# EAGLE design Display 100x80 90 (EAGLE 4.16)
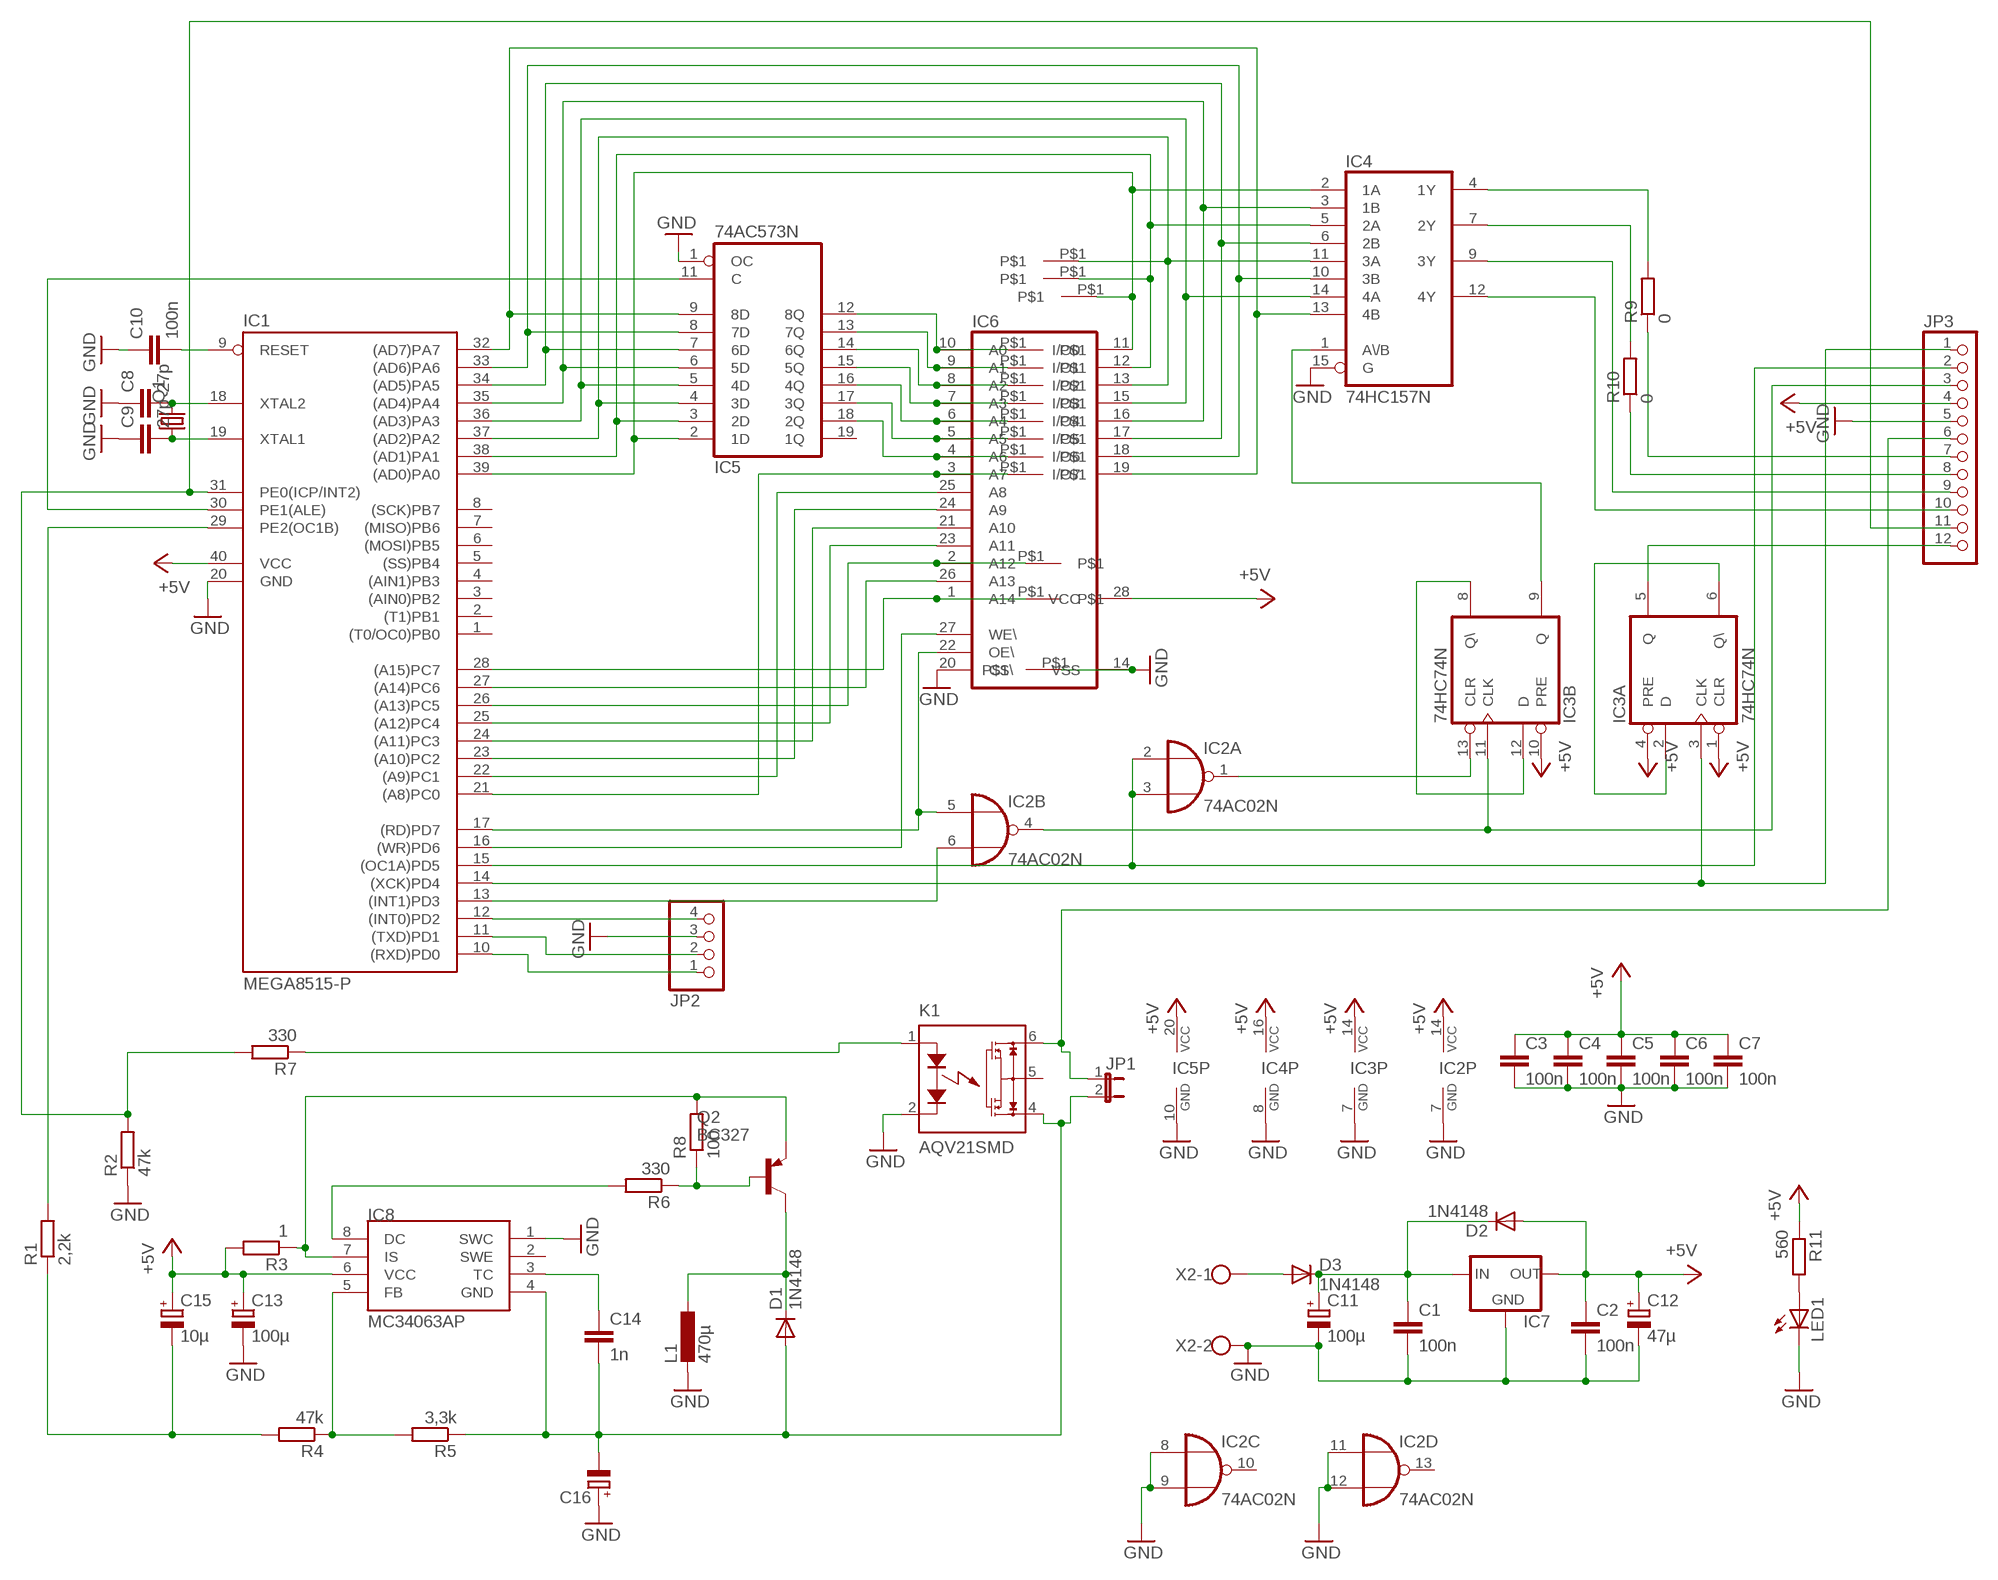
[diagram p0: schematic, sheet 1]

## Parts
C1  100n  C-EUC1206  [C1206]
C2  100n  C-EUC1206  [C1206]
C3  100n  C-EUC1206  [C1206]
C4  100n  C-EUC1206  [C1206]
C5  100n  C-EUC1206  [C1206]
C6  100n  C-EUC1206  [C1206]
C7  100n  C-EUC1206  [C1206]
C8  27p  C-EUC1206  [C1206]
C9  27p  C-EUC1206  [C1206]
C10  100n  C-EUC1206  [C1206]
C11  100µ  CPOL-EUE5-5  [E5-5]
C12  47µ  CPOL-EUE5-5  [E5-5]
C13  100µ  CPOL-EUE5-5  [E5-5]
C14  1n  C-EUC1206  [C1206]
C15  10µ  CPOL-EUE5-5  [E5-5]
C16  CPOL-EUE5-5  [E5-5]
D1  1N4148  [DO35-10]
D2  1N4148  [DO35-10]
D3  1N4148  [DO35-10]
IC1  MEGA8515-P  [DIL40]
IC2  74AC02N  [DIL14]
IC3  74HC74N  [DIL14]
IC4  74HC157N  [DIL16]
IC5  74AC573N  [DIL20]
IC6  62256P  [DIL28-6]
IC7  78XXS  [78XXS]
IC8  MC34063AP  [DIL08]
JP1  JP1E  [JP1]
JP2  PINHD-1X4  [1X04]
JP3  PINHD-1X12  [1X12]
K1  AQV21SMD  [DIL06SMD]
L1  470µ  L-EU0204/7  [0204/7]
LED1  LEDCHIPLED_1206  [CHIPLED_1206]
Q1  CRYSTALHC49U-V  [HC49U-V]
Q2  BC327  [TO92]
R1  2,2k  R-EU_M1206  [M1206]
R2  47k  R-EU_M1206  [M1206]
R3  1  R-EU_M1206  [M1206]
R4  47k  R-EU_M1206  [M1206]
R5  3,3k  R-EU_M1206  [M1206]
R6  330  R-EU_M1206  [M1206]
R7  330  R-EU_M1206  [M1206]
R8  100  R-EU_M1206  [M1206]
R9  0  R-EU_0207/10  [0207/10]
R10  0  R-EU_0207/10  [0207/10]
R11  560  R-EU_M1206  [M1206]
U$2  PAD  [PAD]
U$3  PAD  [PAD]
U$4  PAD  [PAD]
U$5  PAD  [PAD]
U$6  PAD  [PAD]
U$7  PAD  [PAD]
U$8  PAD  [PAD]
U$9  PAD  [PAD]
U$10  PAD  [PAD]
U$11  PAD  [PAD]
U$12  PAD  [PAD]
U$13  PAD  [PAD]
U$14  PAD  [PAD]
U$15  PAD  [PAD]
X2  W237-102  [W237-102]

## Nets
+5V: C2.1 C3.1 C4.1 C5.1 C6.1 C7.1 C12.+ C13.+ C15.+ D2.A IC1.40(VCC) IC2.14(P:VCC) IC3.1(A:CLR) IC3.4(A:PRE) IC3.10(B:PRE) IC3.14(P:VCC) IC4.16(VCC) IC5.20(VCC) IC6.28(VCC) IC7.OUT IC8.6(VCC) JP3.4 R3.2 R11.1
GND: C1.2 C2.2 C3.2 C4.2 C5.2 C6.2 C7.2 C8.1 C9.1 C10.1 C11.- C12.- C13.- C16.+ IC1.20(GND) IC2.7(P:GND) IC2.8(C:I0) IC2.9(C:I1) IC2.11(D:I0) IC2.12(D:I1) IC3.7(P:GND) IC4.8(GND) IC4.15(G) IC5.1(OC) IC5.10(GND) IC6.14(VSS) IC6.20(CS\) IC7.GND IC8.1(SWC) JP2.3 JP3.5 K1.2(K) L1.2 LED1.C R2.1 U$11.P$1 X2.2
N$1: IC1.39((AD0)PA0) IC4.2(1A) IC5.2(1D) IC6.11(I/O0) U$15.P$1
N$2: IC1.38((AD1)PA1) IC4.5(2A) IC5.3(2D) IC6.12(I/O1) U$13.P$1
N$3: IC1.37((AD2)PA2) IC4.11(3A) IC5.4(3D) IC6.13(I/O2) U$8.P$1
N$4: IC1.36((AD3)PA3) IC4.14(4A) IC5.5(4D) IC6.15(I/O3)
N$5: IC1.35((AD4)PA4) IC4.3(1B) IC5.6(5D) IC6.16(I/O4)
N$6: IC1.34((AD5)PA5) IC4.6(2B) IC5.7(6D) IC6.17(I/O5)
N$7: IC1.33((AD6)PA6) IC4.10(3B) IC5.8(7D) IC6.18(I/O6)
N$8: IC1.32((AD7)PA7) IC4.13(4B) IC5.9(8D) IC6.19(I/O7)
N$9: IC5.12(8Q) IC6.10(A0) U$4.P$1
N$10: IC5.13(7Q) IC6.9(A1) U$5.P$1
N$11: IC5.14(6Q) IC6.8(A2) U$6.P$1
N$12: IC5.15(5Q) IC6.7(A3) U$12.P$1
N$13: IC5.16(4Q) IC6.6(A4) U$14.P$1
N$14: IC5.17(3Q) IC6.5(A5) U$7.P$1
N$15: IC5.18(2Q) IC6.4(A6) U$9.P$1
N$16: IC1.21((A8)PC0) IC6.3(A7) U$10.P$1
N$17: IC1.22((A9)PC1) IC6.25(A8)
N$18: IC1.23((A10)PC2) IC6.24(A9)
N$19: IC1.24((A11)PC3) IC6.21(A10)
N$20: IC1.25((A12)PC4) IC6.23(A11)
N$21: IC1.26((A13)PC5) IC6.2(A12) U$3.P$1
N$22: IC1.27((A14)PC6) IC6.26(A13)
N$23: IC1.28((A15)PC7) IC6.1(A14) U$2.P$1
N$24: IC1.16((WR)PD6) IC6.27(WE\)
N$25: IC1.17((RD)PD7) IC2.5(B:I0) IC6.22(OE\)
N$26: IC3.8(B:Q\) IC3.12(B:D)
N$27: IC3.9(B:Q) IC4.1(A\/B)
N$28: IC3.2(A:D) IC3.6(A:Q\)
N$29: IC2.1(A:O) IC3.13(B:CLR)
N$31: IC1.13((INT1)PD3) IC2.6(B:I1)
N$32: C8.2 IC1.18(XTAL2) Q1.2
N$33: C9.2 IC1.19(XTAL1) Q1.1
N$34: C10.2 IC1.9(RESET)
N$35: IC1.31(PE0(ICP/INT2)) JP3.11 R2.2 R7.2
N$36: IC1.15((OC1A)PD5) IC2.2(A:I0) IC2.3(A:I1) JP3.2
N$37: IC1.30(PE1(ALE)) IC5.11(C)
N$38: IC3.5(A:Q) JP3.12
N$39: IC2.4(B:O) IC3.11(B:CLK) JP3.3
N$40: JP3.7 R9.1
N$41: JP3.8 R10.1
N$42: IC4.9(3Y) JP3.9
N$43: IC4.12(4Y) JP3.10
N$45: C14.1 IC8.3(TC)
N$46: C14.2 C16.- D1.A IC8.4(GND) JP1.2 K1.4(D2) R5.1
N$47: C1.1 C11.+ D2.C D3.C IC7.IN
N$48: IC8.5(FB) R4.1 R5.2
N$49: K1.1(A) R7.1
N$50: LED1.A R11.2
N$51: C15.- R1.1 R4.2
N$52: IC1.29(PE2(OC1B)) R1.2
N$53: IC8.8(DC) R6.2
N$54: Q2.2(B) R6.1 R8.1
N$55: IC8.7(IS) Q2.1(E) R3.1 R8.2
N$56: D1.C L1.1 Q2.3(C)
N$57: JP1.1 JP3.6 K1.6(D1)
N$58: IC4.4(1Y) R9.2
N$59: IC4.7(2Y) R10.2
N$60: D3.A X2.1
N$61: IC1.14((XCK)PD4) IC3.3(A:CLK) JP3.1
N$63: IC1.12((INT0)PD2) JP2.4
RXD: IC1.10((RXD)PD0) JP2.1
TXD: IC1.11((TXD)PD1) JP2.2
Unconnected: IC1.1((T0/OC0)PB0) IC1.2((T1)PB1) IC1.3((AIN0)PB2) IC1.4((AIN1)PB3) IC1.5((SS)PB4) IC1.6((MOSI)PB5) IC1.7((MISO)PB6) IC1.8((SCK)PB7) IC2.10(C:O) IC2.13(D:O) IC5.19(1Q) IC8.2(SWE) K1.5(S)

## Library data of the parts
C1-C10 C14 = rcl:C-EU: CAPACITOR, European symbol
C11-C13 C15 C16 = rcl:CPOL-EU: POLARIZED CAPACITOR, European symbol
D1-D3 = diode:1N4148: DIODE
IC1 = atmel:MEGA8515-P: MICROCONTROLLER 8 Kbytes FLASH 512 bytes SRAM 512 bytes EEPROM USART 8-channel 10 bit ADC Source: avr.lbr
IC2 = 74xx-eu:74*02: Quad 2-input NOR gate
IC3 = 74xx-eu:74*74: Dual D type positive edge triggered FLIP FLOP, preset and clear
IC4 = 74xx-eu:74*157: Quadruple 2-line to 1-line data SELECTOR/MULTIPLEXER
IC5 = 74xx-eu:74*573: 8-bit D latch BUS DRIVER
IC6 = memory-hitachi:62256P: MEMORY
IC7 = v-reg:78XXS: VOLTAGE REGULATOR
IC8 = mc34063:MC34063
JP1 = jumper:JP1E: JUMPER
JP2 = pinhead:PINHD-1X4: PIN HEADER
JP3 = pinhead:PINHD-1X12: PIN HEADER
K1 = relay:AQV*: PhotoMOS Relay NAiS Source: http://www.mew-europe.com/.. pti_en.pdf
L1 = rcl:L-EU: INDUCTOR, European symbol
LED1 = led:LED: LED
Q1 = crystal:CRYSTAL: CRYSTAL
Q2 = transistor-pnp:BC327: PNP Transistor
R1-R11 = rcl:R-EU_: RESISTOR, European symbol
U$2-U$15 = special-pad:PAD
X2 = con-wago-500:W237-102: WAGO SCREW CLAMP

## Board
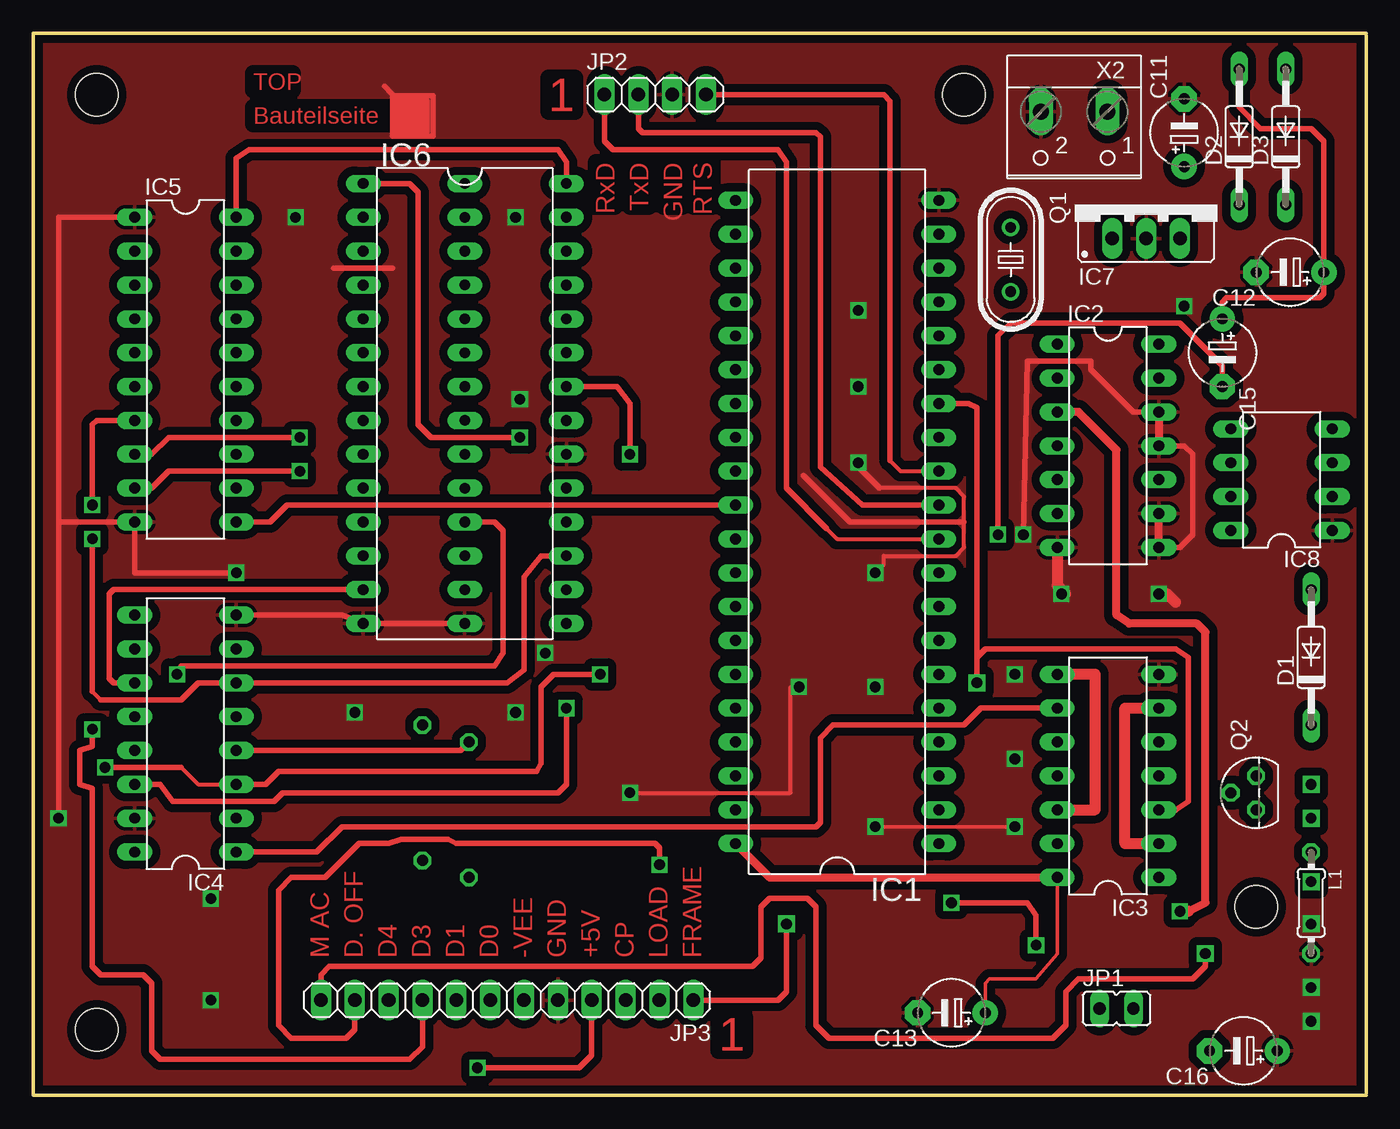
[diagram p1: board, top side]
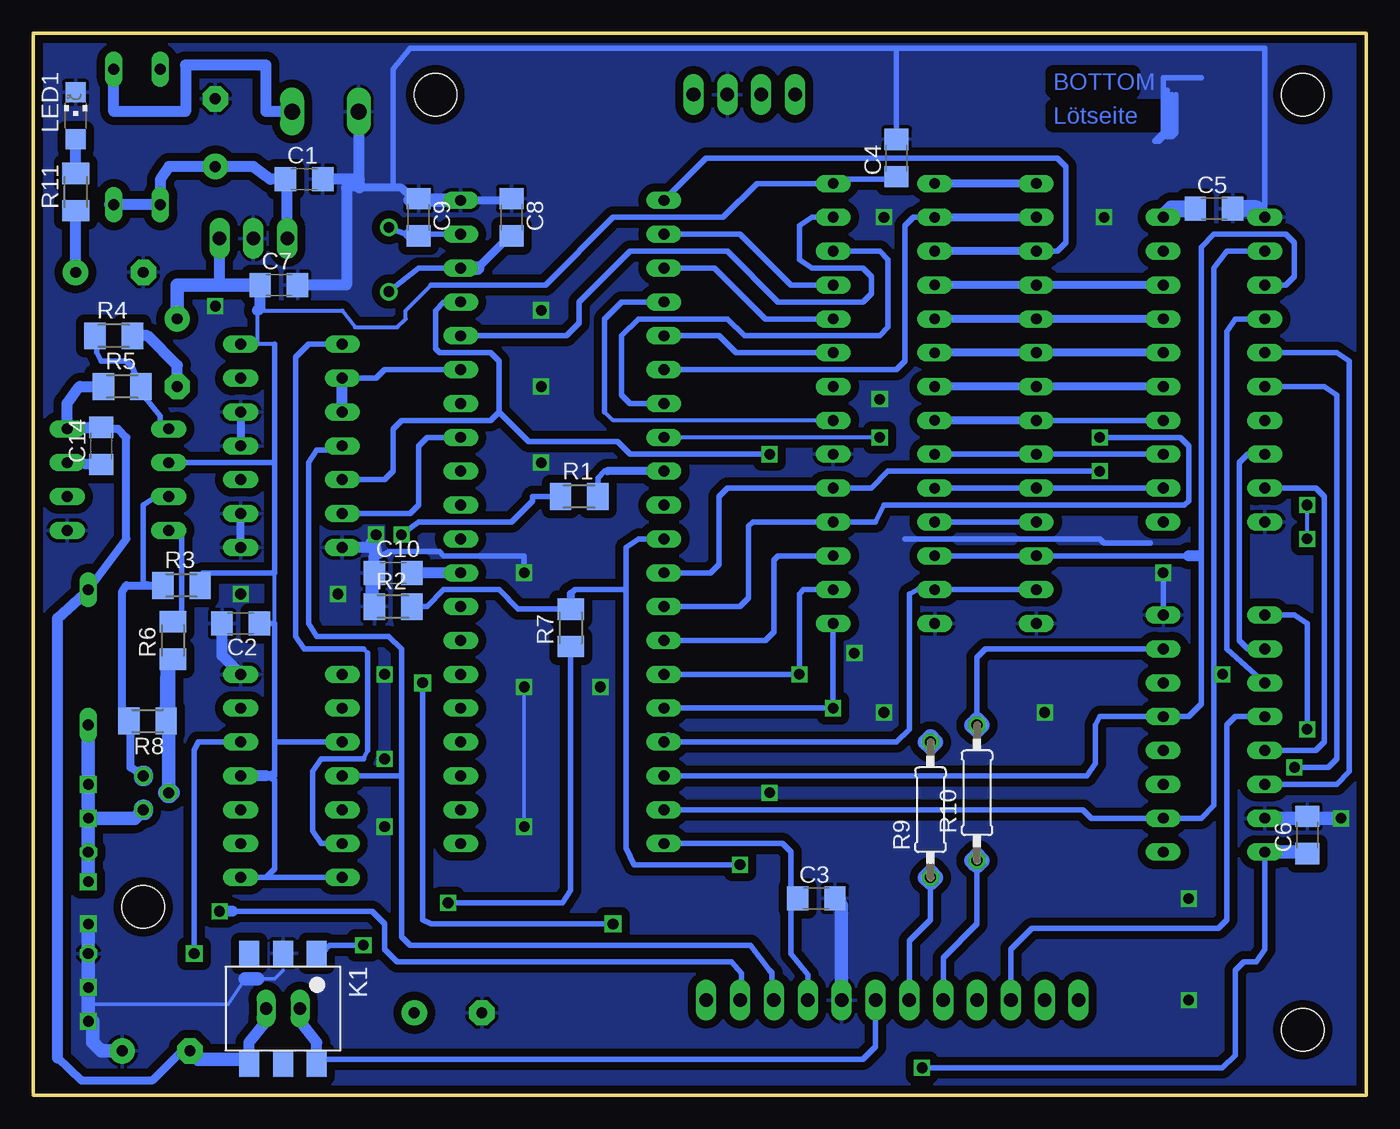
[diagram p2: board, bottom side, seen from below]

Size 100 x 79.68 mm. Coordinates in mm from the lower left corner, seen from the top.
Outline: 99.99,0 0,0 0,79.68 99.99,79.68
Outline: 100,79.53 100,0.15
Copper layers (1*16): Top 0.035mm / dielectric 1.5mm / Bottom 0.035mm
Design rules "default": minimum track width 10mil, minimum drill 24mil, track to track 10mil, track to pad 10mil, pad to pad 10mil, via to via 10mil, smd to smd 10mil, copper to edge 20mil, drill to drill 8mil, minimum pad ring 10mil, minimum via ring 8mil, stop-mask expansion 4mil, vias tented up to drill 0mil, thermal gap 10mil
Holes 3.2 mm at 4.75,75.08 69.83,75.08 4.75,4.92 91.74,14.12

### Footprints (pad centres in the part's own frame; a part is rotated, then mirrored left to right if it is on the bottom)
C1206 = smd 1.6 x 1.8: 1 -1.4,0; 2 1.4,0
E5-5 = drill 0.813 pad 1.905 round: + -2.54,0 | drill 0.813 pad 1.905 octagon: - 2.54,0
DO35-10 = drill 0.813 long: A 5.08,0; C -5.08,0
DIL40 = drill 0.813 long: 1 -24.13,-7.62; 2 -21.59,-7.62; 3 -19.05,-7.62; 4 -16.51,-7.62; 5 -13.97,-7.62; 6 -11.43,-7.62; 7 -8.89,-7.62; 8 -6.35,-7.62; 9 -3.81,-7.62; 10 -1.27,-7.62; 11 1.27,-7.62; 12 3.81,-7.62; 13 6.35,-7.62; 14 8.89,-7.62; 15 11.43,-7.62; 16 13.97,-7.62; 17 16.51,-7.62; 18 19.05,-7.62; 19 21.59,-7.62; 20 24.13,-7.62; 21 24.13,7.62; 22 21.59,7.62; 23 19.05,7.62; 24 16.51,7.62; 25 13.97,7.62; 26 11.43,7.62; 27 8.89,7.62; 28 6.35,7.62; 29 3.81,7.62; 30 1.27,7.62; 31 -1.27,7.62; 32 -3.81,7.62; 33 -6.35,7.62; 34 -8.89,7.62; 35 -11.43,7.62; 36 -13.97,7.62; 37 -16.51,7.62; 38 -19.05,7.62; 39 -21.59,7.62; 40 -24.13,7.62
DIL14 = drill 0.813 long: 1 -7.62,-3.81; 2 -5.08,-3.81; 3 -2.54,-3.81; 4 0,-3.81; 5 2.54,-3.81; 6 5.08,-3.81; 7 7.62,-3.81; 8 7.62,3.81; 9 5.08,3.81; 10 2.54,3.81; 11 0,3.81; 12 -2.54,3.81; 13 -5.08,3.81; 14 -7.62,3.81
DIL16 = drill 0.813 long: 1 -8.89,-3.81; 2 -6.35,-3.81; 3 -3.81,-3.81; 4 -1.27,-3.81; 5 1.27,-3.81; 6 3.81,-3.81; 7 6.35,-3.81; 8 8.89,-3.81; 9 8.89,3.81; 10 6.35,3.81; 11 3.81,3.81; 12 1.27,3.81; 13 -1.27,3.81; 14 -3.81,3.81; 15 -6.35,3.81; 16 -8.89,3.81
DIL20 = drill 0.813 long: 1 -11.43,-3.81; 2 -8.89,-3.81; 3 -6.35,-3.81; 4 -3.81,-3.81; 5 -1.27,-3.81; 6 1.27,-3.81; 7 3.81,-3.81; 8 6.35,-3.81; 9 8.89,-3.81; 10 11.43,-3.81; 11 11.43,3.81; 12 8.89,3.81; 13 6.35,3.81; 14 3.81,3.81; 15 1.27,3.81; 16 -1.27,3.81; 17 -3.81,3.81; 18 -6.35,3.81; 19 -8.89,3.81; 20 -11.43,3.81
DIL28-6 = drill 0.813 long: 1 -16.51,-7.62; 2 -13.97,-7.62; 3 -11.43,-7.62; 4 -8.89,-7.62; 5 -6.35,-7.62; 6 -3.81,-7.62; 7 -1.27,-7.62; 8 1.27,-7.62; 9 3.81,-7.62; 10 6.35,-7.62; 11 8.89,-7.62; 12 11.43,-7.62; 13 13.97,-7.62; 14 16.51,-7.62; 15 16.51,7.62; 16 13.97,7.62; 17 11.43,7.62; 18 8.89,7.62; 19 6.35,7.62; 20 3.81,7.62; 21 1.27,7.62; 22 -1.27,7.62; 23 -3.81,7.62; 24 -6.35,7.62; 25 -8.89,7.62; 26 -11.43,7.62; 27 -13.97,7.62; 28 -16.51,7.62
78XXS = drill 1.016 long: GND 0,-2.54; IN -2.54,-2.54; OUT 2.54,-2.54
DIL08 = drill 0.813 long: 1 -3.81,-3.81; 2 -1.27,-3.81; 3 1.27,-3.81; 4 3.81,-3.81; 5 3.81,3.81; 6 1.27,3.81; 7 -1.27,3.81; 8 -3.81,3.81
JP1 = drill 0.914 long: 1 0,-1.27; 2 0,1.27
1X04 = drill 1.016 long: 1 -3.81,0; 2 -1.27,0; 3 1.27,0; 4 3.81,0
1X12 = drill 1.016 long: 1 -13.97,0; 2 -11.43,0; 3 -8.89,0; 4 -6.35,0; 5 -3.81,0; 6 -1.27,0; 7 1.27,0; 8 3.81,0; 9 6.35,0; 10 8.89,0; 11 11.43,0; 12 13.97,0
DIL06SMD = smd 1.5 x 1.9: 1 -2.54,-4.15; 2 0,-4.15; 3 2.54,-4.15; 4 2.54,4.15; 5 0,4.15; 6 -2.54,4.15
0204/7 = drill 0.813 octagon: 1 -3.81,0; 2 3.81,0
CHIPLED_1206 = smd 1.5 x 1.5: A 0,-1.75; C 0,1.75
HC49U-V = drill 0.813 round: 1 -2.413,0; 2 2.413,0
TO92 = drill 0.813 octagon: 1 1.27,0; 2 0,1.905; 3 -1.27,0
M1206 = smd 1.6 x 2: 1 -1.4,0; 2 1.4,0
0207/10 = drill 0.813 octagon: 1 -5.08,0; 2 5.08,0
PAD = drill 0.8 long: P$1 0,0
W237-102 = drill 1.194 long: 1 -2.5,-1.27; 2 2.5,-1.27

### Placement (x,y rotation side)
C1  79.68,68.73 0 bottom
C2  84.44,35.4 180 bottom
C3  41.26,14.76 0 bottom
C4  35.23,70.32 90 bottom
C5  11.41,66.51 0 bottom
C6  4.43,19.52 90 bottom
C7  81.58,60.8 0 bottom
C8  64.12,65.88 270 bottom
C9  71.11,65.88 270 bottom
C10  73.01,39.2 0 bottom
C11  86.34,72.22 90 top
C12  94.28,61.75 180 top
C13  68.88,6.18 180 top
C14  94.92,48.73 90 bottom
C15  89.2,55.72 270 top
C16  90.79,3.33 180 top
D1  95.87,32.86 90 top
D2  90.47,71.91 90 top
D3  93.97,71.91 90 top
IC1  60.31,43.02 90 top
IC2  80.63,48.73 270 top
IC3  80.63,23.96 90 top
IC4  11.41,27.14 90 top
IC5  11.41,54.45 270 top
IC6  32.37,51.91 270 top
IC7  83.49,66.83 0 top
IC8  93.65,46.19 90 top
JP1  81.27,6.5 270 top
JP2  46.66,75.08 0 top
JP3  35.55,7.14 180 top
K1  81.27,6.5 180 bottom
L1  95.87,14.44 270 top
LED1  96.82,73.49 0 bottom
Q1  73.33,62.7 270 top
Q2  91.74,22.7 90 top
R1  59.04,44.92 0 bottom
R2  73.01,36.66 0 bottom
R3  88.89,38.25 0 bottom
R4  93.97,56.98 0 bottom
R5  93.33,53.18 0 bottom
R6  89.52,34.12 90 bottom
R7  59.67,35.08 90 bottom
R8  91.42,28.09 180 bottom
R9  32.69,21.43 90 bottom
R10  29.2,22.7 90 bottom
R11  96.82,67.78 90 bottom
U$2  32.37,68.41 180 top
U$3  32.37,65.88 180 top
U$4  32.37,45.55 180 top
U$5  32.37,48.09 180 top
U$6  32.37,50.63 180 top
U$7  32.37,58.26 180 top
U$8  32.37,37.94 180 top
U$9  32.37,60.8 180 top
U$10  32.37,63.34 180 top
U$11  32.37,35.4 180 top
U$12  32.37,53.18 180 top
U$13  32.37,40.48 180 top
U$14  32.37,55.72 180 top
U$15  32.37,43.02 180 top
X2  78.09,72.54 180 top

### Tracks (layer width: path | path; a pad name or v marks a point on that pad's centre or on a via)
+5V  (via drill 0.8)
  Top 0.254: C13.+ 71.42,8.41 71.74,8.73 75.23,8.73 76.82,10.63 IC3.14
  Top 0.406: IC5.20 15.22,70.32 16.18,70.95 39.35,70.95 39.99,70 39.99,68.73 | v33.32,2.06 40.94,2.06 41.89,3.01 JP3.4 | D2.A 90.47,74.13 92.06,72.54 95.87,72.54 96.82,71.59 C12.+ 96.82,60.16 96.5,59.84 89.52,59.84 89.2,59.52 C15.+
  Top 0.61: IC6.28 39.99,68.73 | IC1.40 55.23,16.35 IC3.14
  Bottom 0.305: 70.15,60.8 72.06,58.89 72.06,58.26 72.69,57.62 75.87,57.62 76.82,58.89 83.17,58.89 83.17,56.35 | 84.76,56.35 IC2.14 83.17,56.35 | 81.9,56.35 83.17,56.35 | 81.9,35.4 81.9,39.2
  Bottom 0.406: 81.9,24.28 82.53,23.96 82.25,23.82 | 81.9,26.51 IC3.10 | 82.53,16.35 IC3.1 | IC3.14 82.53,16.35 | 82.25,23.82 81.9,23.65 81.9,16.98 82.53,16.35 | 70.15,60.8 61.58,60.8 56.5,65.88 48.24,65.88 45.7,68.41 IC6.28 39.67,68.73 35.04,68.73 | IC1.40 43.8,18.89 43.16,18.25 43.16,15.08 | 43.16,15.08 43.16,10.63 41.89,9.04 JP3.4 | 81.9,47.46 81.9,39.2 87.3,39.2 R3.2 | 81.9,47.46 81.9,56.35 | C3.1 42.85,14.76 43.16,15.08 | C2.1 81.9,35.4 81.9,26.51 | 35.04,68.73 34.91,68.73 | 35.04,68.73 C4.1 | IC4.16 7.61,10.95 8.24,10 9.19,10 9.83,9.36 9.83,3.01 10.78,2.06 v33.32,2.06 | 82.25,23.82 82.25,23.93 81.9,23.96 81.9,24.28 | 81.9,24.28 81.9,26.51 | 81.9,47.46 IC8.6
  Bottom 0.813: 82.53,23.96 IC3.4 | 83.17,58.89 82.98,59.08 C7.1 86.03,60.8 IC7.OUT | 96.82,66.51 R11.1 C12.+
  Bottom 1.016: 4.3,18.25 4.11,18.25 | 4.3,18.25 C6.1 | IC4.16 4.3,18.25 | C15.+ 89.2,60.8 C7.1
  Bottom 1.27: IC5.20 14.59,66.51 C5.1
GND  (via drill 0.8, 0.8 pad 1.27)
  Top 0.254: v63.17,20.16 v73.64,20.16
  Top 0.305: 63.48,45.55 69.2,45.55 69.83,44.92 69.83,43.02 69.83,41.11 69.2,40.48 63.8,40.48 63.8,39.84 v63.17,39.2 | v44.75,22.7 56.82,22.7 56.82,30.63 v57.45,30.63
  Top 0.406: IC4.8 23.16,36.03 IC6.14 U$11.P$1 | 1.89,43.02 IC5.10 7.61,39.2 v15.22,39.2 | 1.89,43.02 1.89,65.88 IC5.1 | v1.89,20.79 1.89,43.02 | v61.9,47.46 61.9,47.14 63.48,45.55 | IC2.8 86.03,41.11 86.98,42.06 86.98,48.09 86.34,48.73 IC2.11 | v74.28,42.06 74.6,55.08 79.36,55.08 79.36,54.45 82.53,51.27 IC2.12 | 69.83,43.02 61.26,43.02 57.77,46.51 | 22.53,62.06 26.97,62.06 | 26.34,75.72 26.97,75.08 26.97,71.97 29.98,71.97 29.98,75 27.18,75 27.18,72.31 29.52,72.31 29.52,74.63 27.45,74.63 27.45,72.64 29.24,72.64 29.24,74.38 27.7,74.38 27.7,72.96 28.98,72.96 28.98,74.04 27.94,74.04 27.94,73.27 28.71,73.27 28.71,73.65 28.23,73.65 28.23,73.76 28.78,73.76
  Top 0.61: IC2.8 IC2.9 | 84.44,51.59 IC2.12 IC2.11
  Top 0.813: IC2.7 76.82,38.25 77.45,37.62 | 85.71,36.98 85.08,37.62
  Bottom 0.254: 84.12,8.73 85.39,6.82 95.87,6.82 | v63.17,20.16 v63.17,30.63 | 83.17,8.73 81.9,8.73 81.27,9.36
  Bottom 0.406: IC5.1 7.61,78.57 35.23,78.57 | 35.23,78.57 71.74,78.57 73.01,76.99 73.01,68.1 72.38,68.1 C9.1 | IC3.7 85.08,31.59 84.76,31.9 | 35.23,78.57 C4.2 | v1.89,20.79 2.52,20.79 | v15.22,39.2 IC4.8 | v74.28,42.06 73.96,40.48 73.33,40.79 69.52,40.79 69.2,40.48 63.17,40.48 v63.17,39.2 | 16.18,41.43 19.67,41.43 19.99,41.74 34.59,41.74 | 12.37,76.35 15.22,76.35 15.22,72.22 15.86,71.59 15.54,71.59 14.91,72.22 | 14.91,72.22 14.91,71.91 14.59,71.91 14.27,72.22 | 14.27,72.22 14.91,72.22 | 14.91,72.86 14.91,72.22 | 14.91,72.86 14.91,75.4 | 14.59,72.54 14.91,72.86 | 14.59,72.54 14.27,72.22 | 14.27,72.22 14.27,72.86 | 14.27,72.86 14.27,75.08 | 14.59,72.54 14.27,72.86 | 14.59,72.54 14.59,75.08
  Bottom 0.61: IC1.20 64.12,67.14 | 71.74,67.46 72.38,68.1 75.55,68.1 76.5,68.1 | v95.87,12.85 95.87,13.17 | IC2.12 IC2.11 | 84.44,43.97 IC2.9 IC2.8
  Bottom 0.813: IC2.7 74.92,41.11 v74.28,42.06 74.6,39.2 C10.1 | C2.2 85.84,32.98 84.76,31.9 IC3.7 | C9.1 71.74,67.46 | C7.2 76.5,60.8 76.5,68.1 | X2.2 75.55,73.81 75.55,68.41 | 75.55,68.1 75.55,68.41 | C1.2 75.55,68.73 75.55,68.41
  Bottom 1.016: 4.43,20.79 IC4.15 | C9.1 71.74,67.14 IC1.20 | 64.12,67.14 C8.1 | 4.43,20.79 C6.2 | 2.52,20.79 4.43,20.79 | R2.1 74.6,36.66 74.6,39.02 C10.1 | C3.2 39.35,14.25 39.35,6.82 | v95.87,12.85 L1.2 v95.87,8.09 95.87,6.82 v95.87,5.55 95.55,5.55 95.55,3.96 94.92,3.33 C16.+ | 83.17,8.73 84.12,8.73
  Bottom 1.27: IC5.1 8.24,66.51 C5.2
  other vias: 36.5,52.22 36.18,65.88 73.64,31.59 86.34,59.21 13.32,7.14 36.18,28.73 13.32,14.76 73.64,25.23 61.9,58.89 61.9,53.18 77.14,37.62 84.44,37.62 19.67,65.88 38.4,33.17 24.11,28.73
  pour Top (isolate 0.61): 100.04,0.16 -0.01,-0.17 -0.01,79.84 100.04,79.85
  pour Bottom (isolate 0.61): 100.04,-0.25 -0.33,-0.48 -0.01,79.84 100.04,79.76
N$1  (via drill 0.8)
  Top 0.406: v10.78,31.59 11.1,32.22 34.59,32.22 35.23,33.17 35.23,42.38 34.59,43.02 U$15.P$1
  Bottom 0.305: 12.37,20.79 IC4.2
  Bottom 0.406: IC5.2 10.46,63.34 11.41,62.06 11.41,31.27 | IC1.39 21.26,21.43 20.62,20.79 | IC4.2 20.62,20.79 | 20.62,20.79 12.37,20.79 11.41,21.74 11.41,31.27 | 11.41,31.27 11.1,31.59 v10.78,31.59 | U$15.P$1 IC6.11
N$2
  Bottom 0.305: 15.54,28.41 15.54,28.09
  Bottom 0.406: IC5.3 6.02,60.8 5.38,61.43 5.38,63.97 6.02,64.6 11.41,64.6 12.37,63.65 12.37,40.48 | 12.37,40.48 12.37,29.36 13.32,28.41 IC4.5 | IC1.38 20.94,23.96 20.3,24.92 20.3,27.78 19.99,28.41 15.54,28.41 | 12.37,40.48 12.68,40.48 IC6.12 U$13.P$1
  Bottom 0.813: 12.68,40.48 13.32,40.48 | IC4.5 15.54,28.41
N$3
  Top 0.406: IC6.13 6.02,37.94 5.7,37.62 5.7,31.27 6.02,30.95 IC4.11
  Bottom 0.406: IC5.4 9.83,58.26 10.46,57.3 10.46,33.49 IC4.11 | IC6.13 U$8.P$1 33.64,37.94 34.27,37.62 34.27,27.46 35.23,26.51 52.37,26.51
  Bottom 0.813: IC1.37 52.37,26.51 52.37,26.82
N$4  (via drill 0.8)
  Top 0.406: v39.99,29.05 39.99,23.33 39.35,22.7 18.72,22.7 18.08,22.06 10.46,22.06 9.51,23.33 IC4.14
  Bottom 0.406: IC1.36 v39.99,29.05 IC6.15 | IC4.14 2.21,23.33 1.26,24.28 1.26,55.08 2.21,55.72 IC5.5
N$5  (via drill 0.8)
  Top 0.305: 17.45,23.33 12.37,23.33 11.1,24.6
  Top 0.406: v42.53,31.59 39.04,31.59 38.09,30.63 38.09,24.92 37.77,24.28 18.4,24.28 17.45,23.33 IC4.3 | v5.38,24.6 11.1,24.6
  Bottom 0.406: IC6.16 42.21,37.94 42.53,37.62 v42.53,31.59 IC1.35 | v5.38,24.6 2.84,24.6 2.21,25.23 2.21,52.54 3.16,53.18 IC5.6
N$6  (via drill 0.8)
  Top 0.305: 4.43,30.32 5.07,29.68 | IC5.7 7.92,50.63
  Top 0.406: IC6.17 38.09,40.48 36.81,38.89 36.81,31.9 35.55,30.95 IC4.6 12.37,30.95 11.1,29.68 5.07,29.68 | 4.43,30.32 v4.43,41.74 | v4.43,44.29 4.43,50.32 4.75,50.63 IC5.7
  Bottom 0.305: v4.43,41.74 v4.43,44.29
  Bottom 0.406: IC6.17 44.12,40.48 44.44,40.16 44.44,34.76 45.07,34.12 IC1.34
N$7  (via drill 0.8)
  Top 0.406: IC5.8 8.88,48.09 10.14,49.37 v19.99,49.37
  Bottom 0.406: 40.31,43.02 46.02,43.02 46.34,42.7 46.34,37.3 46.98,36.66 IC1.33 | 40.31,43.02 IC6.18 | IC4.10 8.88,33.49 9.51,34.12 9.51,47.46 8.88,48.09 IC5.8 | 40.31,43.02 36.81,43.02 36.18,44.29 13.64,44.29 13.32,44.6 13.32,48.73 13.96,49.37 v19.99,49.37
N$8  (via drill 0.8)
  Top 0.406: v19.99,46.83 10.14,46.83 8.88,45.55 IC5.9
  Bottom 0.406: IC1.32 49.2,39.2 48.56,39.84 48.56,44.92 47.93,45.55 IC6.19 37.13,45.55 35.86,46.83 v19.99,46.83 | IC4.13 3.79,25.87 3.16,26.51 3.16,44.92 3.79,45.55 IC5.9
N$9
  Bottom 0.406: IC5.12 IC6.10 U$4.P$1
N$10
  Bottom 0.406: IC5.13 IC6.9 U$5.P$1
N$11
  Bottom 0.406: IC5.14 IC6.8
  Bottom 0.61: IC6.8 U$6.P$1
N$12
  Bottom 0.61: IC5.15 IC6.7 U$12.P$1
N$13
  Bottom 0.61: IC5.16 IC6.6 U$14.P$1
N$14
  Bottom 0.61: IC5.17 IC6.5 U$7.P$1
N$15
  Bottom 0.61: IC5.18 IC6.4 U$9.P$1
  Bottom 1.016: 14.59,60.8 IC5.18
N$16
  Bottom 0.406: IC1.21 49.52,70.32 23.16,70.32 22.53,69.68 22.53,63.97 23.16,63.34 IC6.3
  Bottom 0.61: IC6.3 U$10.P$1
N$17
  Bottom 0.406: IC1.22 46.98,64.6 43.16,60.8 IC6.25
N$18
  Bottom 0.406: IC1.23 48.88,62.06 45.07,58.26 IC6.24
N$19
  Bottom 0.305: 57.13,51.27 56.5,50.63 IC6.21
  Bottom 0.406: IC1.24 55.87,59.52 57.13,58.26 57.13,51.27
N$20
  Bottom 0.406: IC6.23 47.29,55.72 48.56,56.98 IC1.25
N$21
  Bottom 0.406: IC1.26 35.23,54.45 34.59,55.08 34.59,65.24 33.96,65.88 U$3.P$1 32.05,65.88
  Bottom 0.61: 32.05,65.88 IC6.2
N$22
  Bottom 0.406: IC1.27 55.23,51.91 55.87,52.54 55.87,56.98 54.59,58.26 47.93,58.26 46.66,56.98 36.5,56.98 35.86,57.62 35.86,62.7 36.5,63.34 IC6.26
N$23  (via drill 0.8)
  Top 0.406: v36.5,49.37 29.83,49.37 28.88,50.32 28.88,67.78 28.24,68.41 IC6.1
  Bottom 0.305: v36.5,49.37 IC1.28
  Bottom 0.61: IC6.1 U$2.P$1
N$24
  Bottom 0.406: IC6.27 41.58,65.88 42.53,65.24 42.53,62.7 41.58,62.06 37.77,62.06 37.13,61.43 37.13,60.16 37.77,59.52 44.12,59.52 47.93,63.34 55.23,63.34 59.04,59.52 59.04,57.94 59.99,56.98 IC1.16
N$25  (via drill 0.8)
  Top 0.406: v44.75,48.09 44.75,51.91 43.8,53.18 IC6.22 39.67,53.18
  Bottom 0.406: IC2.5 73.64,46.19 73.01,46.83 73.01,50 72.38,50.63 65.71,50.63 65.07,51.27 | 65.07,51.27 65.07,55.08 65.71,55.72 69.52,55.72 69.83,56.03 69.83,58.89 69.2,59.52 IC1.17 67.61,59.52 | 65.07,51.27 62.85,49.05 56.18,49.05 55.23,48.09 v44.75,48.09
N$26
  Top 0.813: IC3.8 79.68,31.59 79.68,21.43 IC3.12
N$27
  Top 0.406: IC3.9 71.11,29.05 69.83,27.78 59.99,27.78 59.04,26.82 59.04,20.47 58.72,20.16 23.16,20.16 21.26,18.25 IC4.1
N$28
  Top 0.813: IC3.6 81.9,29.05 81.9,18.89 IC3.2
N$29
  Bottom 0.305: 75.23,25.23 74.92,25.87 | 74.92,33.17 75.23,33.49
  Bottom 0.406: IC3.13 78.41,18.89 79.04,19.84 79.04,24.28 78.41,25.23 75.23,25.23 | 74.92,25.87 74.92,33.17 | 75.23,33.49 79.68,33.49 80.31,34.44 80.31,55.4 79.36,56.35 IC2.1
N$30
  Bottom 1.27: 90.03,22.7 89.65,22.7 89.77,22.57 89.9,22.57
N$31
  Bottom 0.406: IC1.13 70.47,49.37 71.11,48.73 71.11,44.29 71.74,43.65 IC2.6
N$32
  Bottom 0.406: Q1.2 71.11,62.06 IC1.18
  Bottom 0.61: 64.12,64.6 66.66,62.06
  Bottom 1.016: C8.2 64.12,64.6 | 66.66,62.06 IC1.18
N$33
  Bottom 0.406: Q1.1 72.06,64.6 71.74,64.6 IC1.19
  Bottom 1.016: 71.74,64.6 C9.2
N$34
  Bottom 0.813: IC1.9 C10.2
N$35  (via drill 0.8)
  Top 0.406: JP3.11 24.11,4.92 23.48,4.28 19.35,4.28 18.4,5.23 18.4,15.39 19.35,16.35 21.89,16.35 24.43,18.89 26.66,18.89 27.61,19.2 31.1,19.2 31.73,18.89 46.66,18.89 46.98,18.57 v46.98,17.3
  Bottom 0.406: IC1.31 54.59,41.74 55.55,41.11 55.55,37.94 | 55.55,37.94 55.55,18.57 54.91,17.3 v46.98,17.3 | R7.2 63.62,36.48 65.07,37.94 69.2,37.94 70.47,36.66 R2.2 71.74,36.66 | 59.67,37.62 59.36,37.94 55.55,37.94
  Bottom 0.61: 59.67,37.62 R7.2
  Bottom 1.016: R7.2 59.67,36.35
N$36  (via drill 0.8)
  Top 0.61: IC2.3 78.41,51.27 81.27,48.41 81.27,36.03 82.22,35.4 87.3,35.4 87.93,34.76 87.93,14.44 86.66,13.81
  Top 0.813: v86.03,13.81 86.66,13.81
  Bottom 0.406: IC1.15 73.64,54.45 74.28,53.81 IC2.2 | 85.08,13.81 74.6,13.81 73.64,12.85 73.64,10.95 72.69,10 47.61,10 46.85,9.17 46.85,7.01 JP3.2 46.98,7.46
  Bottom 0.813: IC2.3 IC2.2 | 85.08,13.81 v86.03,13.81
N$37
  Top 0.406: IC1.30 19.04,44.29 17.77,43.02 IC5.11
N$38  (via drill 0.8 pad 1.27)
  Top 0.406: 85.39,8.73 78.41,8.73 77.45,7.77 77.45,5.23 76.5,4.28 59.67,4.28 58.72,5.23 58.72,14.12 58.09,14.76 55.23,14.76 54.59,14.12 54.59,10.31 53.96,9.68 22.21,9.68 21.57,9.04 JP3.12 | 85.39,8.73 86.03,8.73 | 85.39,8.73 86.98,8.73 87.93,9.68 v87.93,10.63
  Bottom 0.406: v87.93,10.63 87.93,25.87 87.61,26.51 IC3.5
N$39
  Bottom 0.305: 76.82,48.41 IC2.4
  Bottom 0.406: 72.38,23.96 72.38,11.9 71.74,11.27 46.21,11.27 44.75,9.36 44.57,9.18 44.57,7.77 | 72.38,23.96 IC3.11 | 72.38,23.96 72.38,33.49 73.33,34.44 78.72,34.44 79.36,35.4 79.36,47.46 78.72,48.41 76.82,48.41 | 44.57,7.77 44.57,7.14 | 44.57,7.77 44.44,7.77 JP3.3
  Bottom 0.813: IC3.11 77.45,23.96
N$40
  Bottom 0.406: 32.69,16.03 32.69,13.17 34.27,11.58 JP3.7
  Bottom 1.27: R9.1 32.69,16.03 32.37,16.35 33.01,16.35 32.69,16.66
N$41
  Bottom 0.406: 29.2,16.03 29.2,16.35 | 29.2,16.03 29.2,17.3 R10.1 | 29.2,16.03 29.2,12.85 31.73,10.31 JP3.8
  Bottom 1.27: 28.88,17.62 R10.1 29.51,17.62 29.2,17.3 29.2,17.93
N$42  (via drill 0.8)
  Top 0.406: v4.43,27.46 4.43,26.19 3.48,25.87 3.48,23.33 4.43,23.01 4.43,9.68 5.07,9.04 8.24,9.04 8.88,8.41 8.88,3.33 9.51,2.69 28.24,2.69 29.2,3.65 JP3.9
  Bottom 0.406: IC4.9 5.38,36.03 4.43,35.4 v4.43,27.46
N$43
  Bottom 0.406: 21.57,12.54 11.1,12.54 10.46,13.17 10.46,27.78 9.83,28.41 IC4.12 | 21.57,12.54 21.71,12.54 | JP3.10 26.66,10.95 25.07,12.54 21.57,12.54
  Bottom 0.813: IC4.12 7.29,28.41
N$44
  Bottom 1.27: 91.68,21.43 91.68,21.55 91.81,21.55 91.68,21.3
N$45
  Bottom 0.813: C14.1 95.74,47.33 IC8.3
N$46
  Bottom 0.406: K1.4 84.44,2.99 83.8,3.33
  Bottom 0.61: D1.A 93.01,41.74 93.01,49.37 93.65,50 IC8.4 95.55,50 | C16.- 88.85,3.33 91.08,1.09 96.37,1.09 98.18,2.8
  Bottom 0.813: C14.2 95.74,50.13 IC8.4 97.46,51.91 96.64,53.05 96.5,53.18 R5.1 94.6,53.18 | 83.8,3.33 83.83,2.35 | 83.8,3.33 83.83,2.69 | JP1.2 82.53,5.55 83.8,3.96 83.8,3.33 | K1.4 83.8,3.33 | 95.81,37.94 95.76,37.99 | 95.81,37.94 D1.A | 98.18,2.8 98.18,35.81 95.81,37.94
  Bottom 1.016: 83.83,2.69 87.61,2.69 C16.-
N$47
  Bottom 0.813: 94.28,66.83 D3.C D2.C 90.47,68.73 89.84,69.68 C11.+ 83.49,69.68 82.22,68.73 C1.1 80.95,68.73 IC7.IN
N$48
  Bottom 0.406: R4.1 95.23,56.98 95.23,55.72 94.92,55.08 93.01,55.08 92.56,54.63 R5.2 92.06,53.18 92.06,52.54 91.74,52.54 90.47,50.95 90.47,50.32 90.16,50 IC8.5 89.52,50
N$49  (via drill 0.8)
  Top 0.406: v68.88,14.44 74.6,14.44 75.23,13.49 v75.23,11.27
  Bottom 0.406: R7.1 59.67,15.39 60.31,14.44 v68.88,14.44 | 78.09,10.95 78.06,10.92 | v75.23,11.27 77.77,11.27 78.09,10.95 | K1.1 78.72,10.63 78.41,10.63 78.09,10.95
N$50
  Bottom 0.813: R11.2 LED1.A
N$51  (via drill 0.8)
  Top 0.406: v72.38,42.06 72.38,56.98 73.33,57.94 86.03,57.94 89.2,54.76 C15.-
  Bottom 0.406: R1.1 62.53,44.92 62.53,44.6 64.12,43.02 71.11,43.02 v72.38,42.06
  Bottom 0.813: R4.2 91.42,56.98 89.2,54.76 C15.- 89.2,52.86
N$52
  Bottom 0.406: 56.95,46.83 57.13,46.83 57.64,46.32 R1.2
  Bottom 0.61: IC1.29 56.95,46.83
N$53
  Bottom 0.406: R6.2 88.89,36.16 88.89,42.38 IC8.8
N$54
  Bottom 0.61: R6.1 89.71,32.54 89.84,32.54 89.97,32.54
  Bottom 1.016: Q2.2 89.84,32.54 | 89.97,32.54 R8.1
N$55
  Bottom 0.406: R3.1 91.74,38.38 91.74,44.29 90.79,44.92 IC8.7
  Bottom 0.61: Q2.1 92.69,24.6 92.69,28.09 | R3.1 93.01,38.25 93.33,37.75 93.33,27.78 92.56,27.78 92.69,28.09 | 92.69,28.09 R8.2
N$56  (via drill 0.8 pad 1.27)
  Bottom 1.016: v95.87,16.03 L1.1 v95.87,20.79 | v95.87,20.79 v95.87,23.33 D1.C | Q2.3 92.38,20.79 v95.87,20.79
N$57
  Bottom 0.406: 78.7,2.72 78.72,2.38 78.41,2.69 37.77,2.69 36.81,3.65 JP3.6
  Bottom 0.813: JP1.1 80,5.55 78.72,3.96 78.72,2.38 K1.6
N$58
  Top 0.406: R9.2 32.05,25.87 IC4.4 14.91,25.87
  Bottom 1.27: 32.69,26.82 R9.2 32.69,26.19 32.37,26.51 33.01,26.51
N$59
  Bottom 0.406: IC4.7 28.56,33.49 29.2,32.86 29.2,28.09
  Bottom 1.27: 29.2,27.46 R10.2 29.2,28.09 28.88,27.78 29.51,27.78
N$60
  Bottom 0.813: X2.1 82.53,73.81 82.53,77.3 88.57,77.3 88.57,73.81 93.97,73.81 D3.A 93.97,77.3
N$61  (via drill 0.8 pad 1.27)
  Top 0.406: IC1.14 70.15,51.91 70.79,51.59 70.79,32.86 | v70.79,30.95 70.79,32.86 | 49.83,7.14 49.4,7.25 JP3.1 49.83,7.14 | 49.83,7.14 55.87,7.14 56.5,7.77 v56.5,12.85 | IC3.3 85.71,21.43 86.66,22.06 86.66,32.86 85.71,33.49 71.42,33.49 70.79,32.86
  Bottom 0.406: v70.79,30.95 70.79,13.17 70.15,12.85 v56.5,12.85
N$62
  Bottom 1.27: 91.68,23.96 91.81,24.09 91.68,24.09 91.68,23.84 91.81,23.84
N$63
  Top 0.305: 64.28,47.62 65.07,46.83 IC1.12
  Top 0.406: 64.28,47.62 64.28,74.6 63.8,75.08 JP2.4
RXD
  Top 0.305: 59.51,42.54 60.31,41.74 IC1.10
  Top 0.406: 59.51,42.54 56.5,45.55 56.5,70 55.87,70.95 43.48,70.95 42.85,71.59 JP2.1
TXD
  Top 0.406: IC1.11 62.21,44.29 59.04,47.14 59.04,71.91 58.72,72.22 45.7,72.22 45.39,72.54 JP2.2

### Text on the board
Top: 1 | TOP | Bauteilseite | RxD | TxD | GND | RTS | M AC | D. OFF | D4 | D3 | D1 | D0 | -VEE | GND | +5V | CP | LOAD | FRAME | 1
Bottom: BOTTOM | Lötseite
